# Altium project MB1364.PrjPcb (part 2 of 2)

## Sheet USB.SchDoc: USB
size A4; Date: Not used; ApprovedBy: Not used; CheckedBy: Not used; Author: Not used; CompanyName: STMicroelectronics; DrawnBy: Not used; Engineer: Not used; Organization: Not used; Address1: Not used; Address2: Not used; Address3: Not used; Address4: Not used; DocumentNumber: 7; Revision: Not used; SheetNumber: 7; SheetTotal: 9
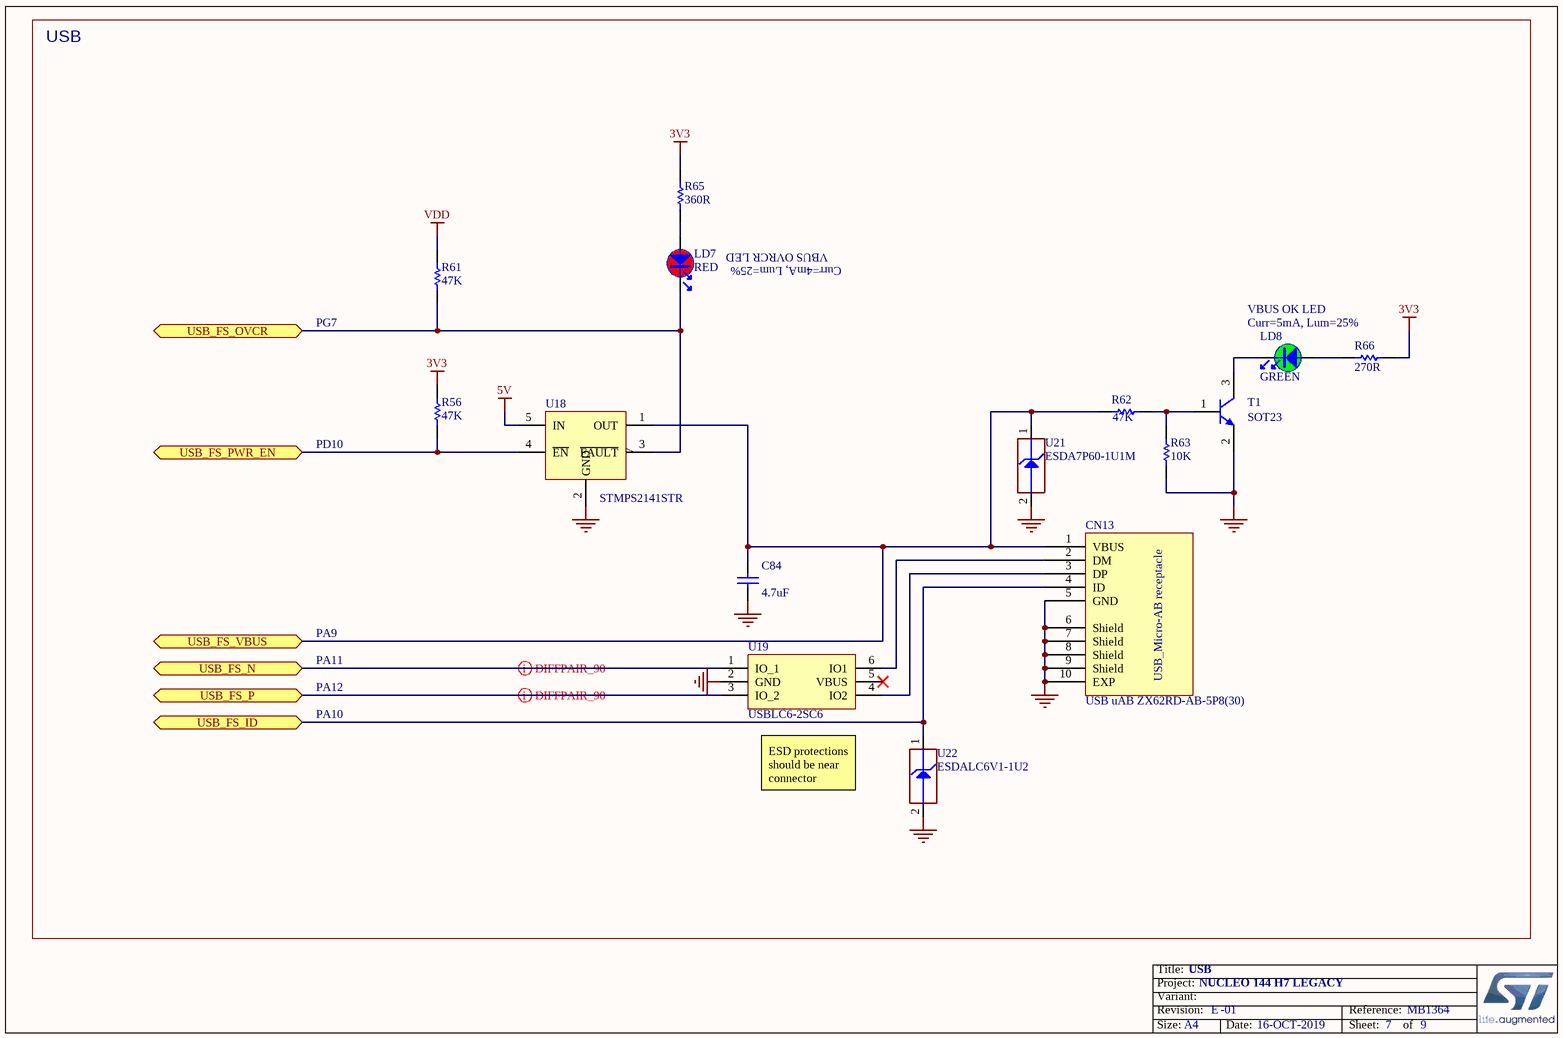
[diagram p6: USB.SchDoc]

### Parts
C84  value 4.7uF  [C0603]  (hidden comment: Capacitor)
CN13  value USB uAB ZX62RD-AB-5P8(30)  [CON_USBMICROAB_MOLEX_47590-0001_H3]  (hidden comment: USB_uAB_47590.0001)
LD7  value RED  [LED_0603_VISHAY_VLMS1300-GS08_RED_1A2K_H0P8]  (hidden comment: LED_red)
LD8  value GREEN  [LED_0603_OSRAM_LG-Q396-PS-35_GREEN_1A2K_H0P4]  (hidden comment: LED_green)
R56  value 47K  [R0402]  (hidden comment: Resistor)
R61  value 47K  [R0402]  (hidden comment: Resistor)
R62  value 47K  [R0402]  (hidden comment: Resistor)
R63  value 10K  [R0402]  (hidden comment: Resistor)
R65  value 360R  [R0402]  (hidden comment: Resistor)
R66  value 270R  [R0402]  (hidden comment: Resistor)
T1  value SOT23  [NPN_SOT23]  (hidden comment: 9013-SOT23)
U18  STMPS2141STR  [MOS_SOT23-5L]
U19  USBLC6-2SC6  [ESD_SOT23-6L]
U21  value ESDA7P60-1U1M  [ESD_QFN2_1P6X1_P125]  (hidden comment: ESD-TRANSIL)
U22  value ESDALC6V1-1U2  [ESD_ST0201]  (hidden comment: ESD-TRANSIL)

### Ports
USB_FS_ID, USB_FS_N, USB_FS_OVCR, USB_FS_P, USB_FS_PWR_EN, USB_FS_VBUS

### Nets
3V3: R56.1 R65.2 R66.2
5V: U18.5(IN)
GND: C84.1 CN13.5(GND) CN13.6(Shield) CN13.7(Shield) CN13.8(Shield) CN13.9(Shield) CN13.10(EXP) R63.1 T1.2(E) U18.2(GND) U19.2(GND) U21.2(GND) U22.2(GND)
VDD: R61.1
USB_FS_ID: CN13.4(ID) U22.1(IO1) ; port USB_FS_ID
USB_FS_N: U19.1(IO_1) ; port USB_FS_N
USB_FS_OVCR: LD7.2 R61.2 U18.3(~{FAULT}) ; port USB_FS_OVCR
USB_FS_P: U19.3(IO_2) ; port USB_FS_P
USB_FS_PWR_EN: R56.2 U18.4(~{EN}) ; port USB_FS_PWR_EN
USB_FS_VBUS: C84.2 CN13.1(VBUS) R62.1 U18.1(OUT) U21.1(IO1) ; port USB_FS_VBUS
NetCN13_2: CN13.2(DM) U19.6(IO1)
NetCN13_3: CN13.3(DP) U19.4(IO2)
NetLD7_1: LD7.1 R65.1
NetLD8_1: LD8.1 R66.1
NetLD8_2: LD8.2 T1.3(C)
NetR62_2: R62.2 R63.2 T1.1(B)

Not connected (* = marked no-connect by the designer): U19 5(VBUS)*

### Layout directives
differential pair: USB_FS_N, USB_FS_P

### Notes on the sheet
- USB
- VBUS OVRCR LED
- Curr=4mA, Lum=25%
- VBUS OK LED
- PG7
- Curr=5mA, Lum=25%
- PD10
- PA9
- PA11
- PA12
- PA10
- (near U19) ESD protections should be near connector

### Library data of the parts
C84 = MCD-00009: Capacitor, MLCC, 4.7uF, 16V, X5R, 10%, 0603, T=0.8mm; Manufacturer_Part_Number: CC0603KRX5R7BB475; Manufacturer: YAGEO; Provided_By: SUBCO; ECCN_US: EAR99; ECCN_EU: NEC
CN13 = MCD-00661: USB-MICRO-AB Receptacle, RA, SMT + DIP, Standard, Top Mount, USB certified (symbol & footprint compatible with MCD-00022); Part_Type: Connector; Manufacturer_Part_Number: ZX62RD-AB-5P8(30); Manufacturer: HIROSE; Provided_By: SUBCO
LD7 = MCD-00587: LED Red, 0603 SMD, 2V Forward Voltage; Part_Type: Display; Manufacturer_Part_Number: VLMS1300-GS08; Manufacturer: VISHAY; Alternate_Manufacturer_Part_Number: LS Q976-NR-1; Alternate_Manufacturer: OSRAM OPTO SEMICONDUCTORS; Provided_By: SUBCO
LD8 = MCD-00588: LED Green, 0603 SMD, Forward Voltage Typ=2V, Max=2.5V; Part_Type: Display; Manufacturer_Part_Number: LG Q396-PS-35; Manufacturer: OSRAM OPTO SEMICONDUCTORS; Alternate_Manufacturer_Part_Number: VLMTG1300-GS08; Alternate_Manufacturer: VISHAY SEMICONDUCTOR OPTO DIVISION; Provided_By: SUBCO
R56 R61 R62 = MCD-00063: Resistor,47K,0402,1%,1/16W; Manufacturer_Part_Number: RC0402FR-0747KL; Manufacturer: YAGEO; Provided_By: SUBCO; ECCN_US: EAR99; ECCN_EU: NEC
R63 = MCD-00053: Resistor,10K,0402,1%,1/16W; Manufacturer_Part_Number: RC0402FR-0710KL; Manufacturer: YAGEO; Provided_By: SUBCO; ECCN_US: EAR99; ECCN_EU: NEC
R65 = MCD-00461: Resistor,360R,0402,1%,1/16W; Manufacturer_Part_Number: RC0402FR-07360RL; Manufacturer: YAGEO; Provided_By: SUBCO; ECCN_US: EAR99; ECCN_EU: NEC
R66 = MCD-00441: Resistor,270R,0402,1%,1/16W; Manufacturer_Part_Number: RC0402FR-07270RL; Manufacturer: YAGEO; Provided_By: SUBCO; ECCN_US: EAR99; ECCN_EU: NEC
T1 = MCD-00073: NPN Bipolar Transistor; Manufacturer_Part_Number: BSR14; Manufacturer: ON SEMICONDUCTOR; Part_Type: IC; Alternate_Manufacturer_Part_Number: MMBT2222ALT1G / MMBT2222ALT3G; Provided_By: SUBCO; ECCN_US: EAR99; ECCN_EU: NEC
U18 = MCD-00083: Enhanced single channel power switches with active low enable pin; Part_Type: IC; Manufacturer: STMICROELECTRONICS; Alternate_Manufacturer_Part_Number: TPS2041C; Alternate_Manufacturer: TEXAS INSTRUMENTS; BMS_Part_Number: 9159003; Provided_By: SUBCO with ST control; ECCN_US: EAR99; ECCN_EU: NEC
U19 = MCD-00163: Very low capacitance ESD protection; Part_Type: IC; Manufacturer: STMICROELECTRONICS; BMS_Part_Number: 9151075; Provided_By: SUBCO with ST control; ECCN_US: EAR99; ECCN_EU: NEC
U21 = MCD-00251: High power transient voltage suppressor, 7V breakdown; Part_Type: Diode; Manufacturer: STMICROELECTRONICS; BMS_Part_Number: 9179042; Provided_By: SUBCO with ST control; ECCN_US: EAR99; ECCN_EU: NEC
U22 = MCD-00170: ESD protection 6V1; Part_Type: Diode; Manufacturer: STMICROELECTRONICS; BMS_Part_Number: 9151132; Provided_By: SUBCO with ST control; ECCN_US: EAR99; ECCN_EU: NEC

## Sheet Ethernet.SchDoc: Ethernet PHY with RJ45 connector
size A4; Date: Not used; ApprovedBy: Not used; CheckedBy: Not used; Author: Not used; CompanyName: STMicroelectronics; DrawnBy: Not used; Engineer: Not used; Organization: Not used; Address1: Not used; Address2: Not used; Address3: Not used; Address4: Not used; DocumentNumber: 6; Revision: Not used; SheetNumber: 6; SheetTotal: 9
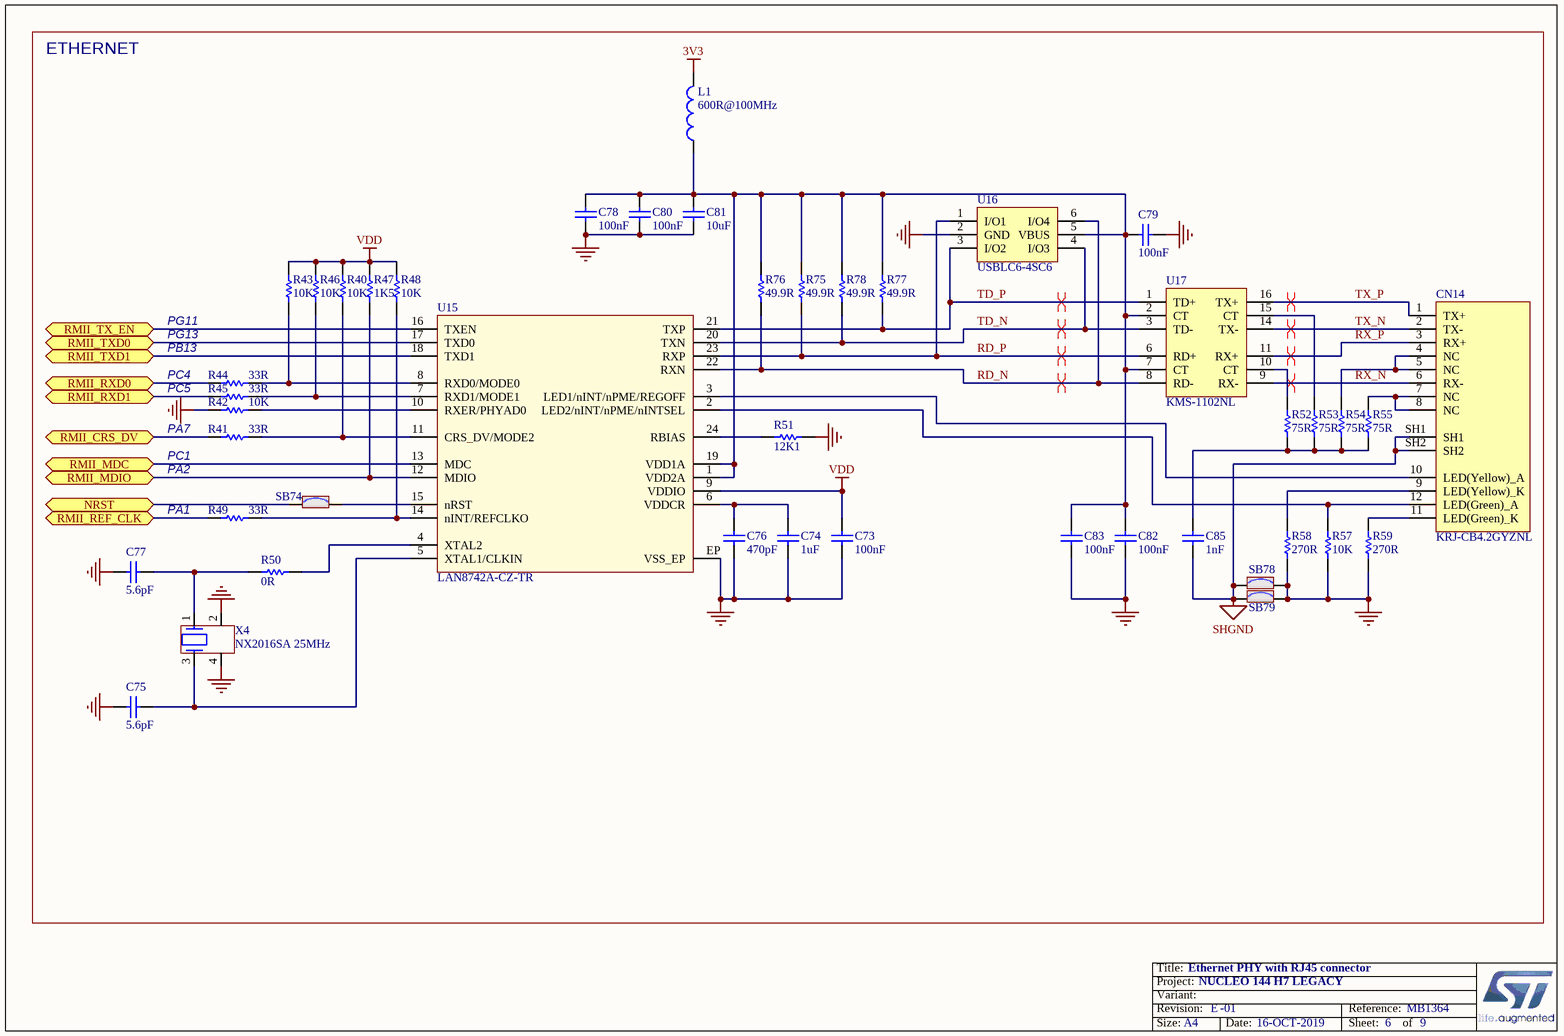
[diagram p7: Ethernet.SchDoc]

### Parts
C73  value 100nF  [C0603]  (hidden comment: Capacitor)
C74  value 1uF  [C0402]  (hidden comment: Capacitor)
C75  value 5.6pF  [C0402]  (hidden comment: Capacitor)
C76  value 470pF  [C0402]  (hidden comment: Capacitor)
C77  value 5.6pF  [C0402]  (hidden comment: Capacitor)
C78  value 100nF  [C0603]  (hidden comment: Capacitor)
C79  value 100nF  [C0603]  (hidden comment: Capacitor)
C80  value 100nF  [C0603]  (hidden comment: Capacitor)
C81  value 10uF  [C0603]  (hidden comment: Capacitor)
C82  value 100nF  [C0603]  (hidden comment: Capacitor)
C83  value 100nF  [C0603]  (hidden comment: Capacitor)
C85  value 1nF  [C1206_H1P6]  (hidden comment: Capacitor)
CN14  value KRJ-CB4.2GYZNL  [CON_RJ45_DGKYD_KRJ-CB4.2GYZNL]  (hidden comment: RJ45_KRJ-CB4.2GYZNL)
L1  value 600R@100MHz  [L0603]  (hidden comment: BEAD)
R40  value 10K  [R0402]  (hidden comment: Resistor)
R41  value 33R  [R0402]  (hidden comment: Resistor)
R42  value 10K  [R0402]  (hidden comment: Resistor)
R43  value 10K  [R0402]  (hidden comment: Resistor)
R44  value 33R  [R0402]  (hidden comment: Resistor)
R45  value 33R  [R0402]  (hidden comment: Resistor)
R46  value 10K  [R0402]  (hidden comment: Resistor)
R47  value 1K5  [R0402]  (hidden comment: Resistor)
R48  value 10K  [R0402]  (hidden comment: Resistor)
R49  value 33R  [R0402]  (hidden comment: Resistor)
R50  value 0R  [R0402]  (hidden comment: Resistor)
R51  value 12K1  [R0402]  (hidden comment: Resistor)
R52  value 75R  [R0402]  (hidden comment: Resistor)
R53  value 75R  [R0402]  (hidden comment: Resistor)
R54  value 75R  [R0402]  (hidden comment: Resistor)
R55  value 75R  [R0402]  (hidden comment: Resistor)
R57  value 10K  [R0402]  (hidden comment: Resistor)
R58  value 270R  [R0402]  (hidden comment: Resistor)
R59  value 270R  [R0402]  (hidden comment: Resistor)
R75  value 49.9R  [R0402]  (hidden comment: Resistor)
R76  value 49.9R  [R0402]  (hidden comment: Resistor)
R77  value 49.9R  [R0402]  (hidden comment: Resistor)
R78  value 49.9R  [R0402]  (hidden comment: Resistor)
SB74  SB_ON  [SOLDER-BRIDGE_R0603-0R]  (value not drawn)
SB78  SB_ON  [SOLDER-BRIDGE_R0603-0R]  (value not drawn)
SB79  SB_ON  [SOLDER-BRIDGE_R0603-0R]  (value not drawn)
U15  LAN8742A-CZ-TR  [ICC_VQFN24-EPAD_4X4_P050]
U16  USBLC6-4SC6  [ESD_SOT23-6L]
U17  KMS-1102NL  [TRS_DGKYD_KMS-1102NL]
X4  value NX2016SA 25MHz  [CRY_NX2016SA_4P]  (hidden comment: XTAL_4_PINS)

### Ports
NRST (bidir), RMII_CRS_DV (bidir), RMII_MDC (bidir), RMII_MDIO (bidir), RMII_REF_CLK (bidir), RMII_RXD0 (bidir), RMII_RXD1 (bidir), RMII_TX_EN (bidir), RMII_TXD0 (bidir), RMII_TXD1 (bidir)

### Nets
3V3: L1.2
GND: C73.1 C74.1 C75.1 C76.1 C77.1 C78.1 C79.2 C80.1 C81.1 C82.1 C83.1 R42.2 R51.2 R57.1 R58.1 R59.1 SB78.2 SB79.2 U15.EP(VSS_EP) U16.2(GND) X4.2 X4.4
SHGND: C85.1 CN14.SH1 CN14.SH2 SB78.1 SB79.1
VDD: C73.2 R40.2 R43.2 R46.2 R47.2 R48.2 U15.9(VDDIO)
NRST: SB74.1 ; port NRST
RD_N: R76.1 U15.22(RXN) U16.6(I/O4) U17.8(RD-)
RD_P: R75.1 U15.23(RXP) U16.1(I/O1) U17.6(RD+)
RMII_CRS_DV: R41.1 ; port RMII_CRS_DV
RMII_MDC: U15.13(MDC) ; port RMII_MDC
RMII_MDIO: R47.1 U15.12(MDIO) ; port RMII_MDIO
RMII_REF_CLK: R49.1 ; port RMII_REF_CLK
RMII_RXD0: R44.1 ; port RMII_RXD0
RMII_RXD1: R45.1 ; port RMII_RXD1
RMII_TX_EN: U15.16(TXEN) ; port RMII_TX_EN
RMII_TXD0: U15.17(TXD0) ; port RMII_TXD0
RMII_TXD1: U15.18(TXD1) ; port RMII_TXD1
RX_N: CN14.6(RX-) U17.9(RX-)
RX_P: CN14.3(RX+) U17.11(RX+)
TD_N: R78.1 U15.20(TXN) U16.4(I/O3) U17.3(TD-)
TD_P: R77.1 U15.21(TXP) U16.3(I/O2) U17.1(TD+)
TX_N: CN14.2(TX-) U17.14(TX-)
TX_P: CN14.1(TX+) U17.16(TX+)
NetC74_2: C74.2 C76.2 U15.6(VDDCR)
NetC75_2: C75.2 U15.5(XTAL1/CLKIN) X4.3
NetC77_2: C77.2 R50.1 X4.1
NetC78_2: C78.2 C79.1 C80.2 C81.2 C82.2 C83.2 L1.1 R75.2 R76.2 R77.2 R78.2 U15.1(VDD2A) U15.19(VDD1A) U16.5(VBUS) U17.2(CT) U17.7(CT)
NetC85_2: C85.2 R52.1 R53.1 R54.1 R55.1
NetCN14_4: CN14.4(NC) CN14.5(NC) R54.2
NetCN14_7: CN14.7(NC) CN14.8(NC) R55.2
NetCN14_9: CN14.9(LED(Yellow)_K) R58.2
NetCN14_10: CN14.10(LED(Yellow)_A) U15.3(LED1/nINT/nPME/REGOFF)
NetCN14_11: CN14.11(LED(Green)_K) R59.2
NetCN14_12: CN14.12(LED(Green)_A) R57.2 U15.2(LED2/nINT/nPME/nINTSEL)
NetR40_1: R40.1 R41.2 U15.11(CRS_DV/MODE2)
NetR42_1: R42.1 U15.10(RXER/PHYAD0)
NetR43_1: R43.1 R44.2 U15.8(RXD0/MODE0)
NetR45_2: R45.2 R46.1 U15.7(RXD1/MODE1)
NetR48_1: R48.1 R49.2 U15.14(nINT/REFCLKO)
NetR50_2: R50.2 U15.4(XTAL2)
NetR51_1: R51.1 U15.24(RBIAS)
NetR52_2: R52.2 U17.10(CT)
NetR53_2: R53.2 U17.15(CT)
NetSB74_2: SB74.2 U15.15(nRST)

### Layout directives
differential pair: RD_N, RD_P, RX_N, RX_P, TD_N, TD_P, TX_N, TX_P

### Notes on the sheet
- ETHERNET
- PG11
- PG13
- PB13
- PC4
- PC5
- PA7
- PC1
- PA2
- (near R49) PA1

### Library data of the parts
C73 C78-C80 C82 C83 = MCD-00237: Capacitor, MLCC, 100nF, 6V3, X5R, 10%, 0603, T=0,8mm; Manufacturer_Part_Number: CC0603KRX5R5BB104; Manufacturer: YAGEO; Provided_By: SUBCO; ECCN_US: EAR99; ECCN_EU: NEC
C74 = MCD-00095: Capacitor, MLCC, 1uF, 6V3, X5R, 10%, 0402, T=0,5mm; Manufacturer_Part_Number: GRM155R61E105KA12; Manufacturer: MURATA; Alternate_Manufacturer_Part_Number: GRM155R60J105KE19; Provided_By: SUBCO; ECCN_US: EAR99; ECCN_EU: NEC
C75 C77 = MCD-01374: Capacitor, MLCC, 5.6pF, 50V, NPO, 5%, 0402, T=0,5mm; Manufacturer_Part_Number: CC0402BRNPO9BN5R6; Manufacturer: YAGEO; Provided_By: SUBCO
C76 = MCD-00724: Capacitor, MLCC, 470pF, 50V, NPO, 5%, 0402, T=0,5mm; Manufacturer_Part_Number: CC0402JRNPO9BN471; Manufacturer: YAGEO; Provided_By: SUBCO
C81 = MCD-01124: Capacitor, MLCC, 10µF, 10V, X5R, 10%, 0603, T=0.8mm; Manufacturer_Part_Number: GRM188R61A106KAAL; Manufacturer: MURATA; Provided_By: SUBCO; ECCN_US: EAR99; ECCN_EU: NEC
C85 = MCD-00722: Capacitor, MLCC, 1nF, 2KV, X7R, 10%, 1206, T=1,25mm; Manufacturer_Part_Number: CC1206KKX7RDBB102; Manufacturer: YAGEO; Provided_By: SUBCO
CN14 = MCD-00717: RJ45 jack, single port, with LEDS, Metal shielded dip low profile; Part_Type: Connector; Manufacturer: DONGGUAN KEYOUDA ELECTRONIC TECHNOLOGY; Provided_By: SUBCO
L1 = MCD-00047: SMD Chip ferrite bead, 600R@100MHz +/-25%, 350mA, 500mohm DC, 0603, T=0.8mm; Part_Type: Inductor; Manufacturer_Part_Number: FCM1608KF-601T03; Manufacturer: TAI-TECH; Provided_By: SUBCO
R40 R42 R43 R46 R48 R57 = MCD-00053: as R63 on sheet USB
R41 R44 R45 R49 = MCD-00455: Resistor,33R,0402,1%,1/16W; Manufacturer_Part_Number: RC0402FR-0733RL; Manufacturer: YAGEO; Provided_By: SUBCO; ECCN_US: EAR99; ECCN_EU: NEC
R47 = MCD-00068: Resistor,1K5,0402,1%,1/16W; Manufacturer_Part_Number: RC0402FR-071K5L; Manufacturer: YAGEO; Provided_By: SUBCO; ECCN_US: EAR99; ECCN_EU: NEC
R50 = MCD-00052: Resistor,0R,0402,5%,1/16W; Manufacturer_Part_Number: RC0402JR-070RL; Manufacturer: YAGEO; Provided_By: SUBCO; ECCN_US: EAR99; ECCN_EU: NEC
R51 = MCD-00723: Resistor,12K1,0402,1%,1/16W; Manufacturer_Part_Number: RC0402FR-0712K1L; Manufacturer: YAGEO; Provided_By: SUBCO; ECCN_US: EAR99; ECCN_EU: NEC
R52-R55 = MCD-00515: Resistor,75R,0402,1%,1/16W; Manufacturer_Part_Number: RC0402FR-0775RL; Manufacturer: YAGEO; Provided_By: SUBCO; ECCN_US: EAR99; ECCN_EU: NEC
R58 R59 = MCD-00441: as R66 on sheet USB
R75-R78 = MCD-00565: Resistor,49R9,0402,1%,1/16W; Manufacturer_Part_Number: RC0402FR-0749R9L; Manufacturer: YAGEO; Provided_By: SUBCO; ECCN_US: EAR99; ECCN_EU: NEC
SB74 SB78 SB79 = MCD-00071: Solder Bridge ON; Part_Type: Mechanical; Manufacturer_Part_Number: RC0603JR-070RL; Manufacturer: YAGEO; Provided_By: SUBCO
U15 = MCD-00719: 10/100M RMII Ethernet transceiver; Part_Type: IC; Manufacturer: MICROCHIP; Provided_By: SUBCO
U16 = MCD-00250: Very low capacitance ESD protection , 4 lines; Part_Type: IC; Manufacturer: STMICROELECTRONICS; BMS_Part_Number: 9151001; Provided_By: SUBCO with ST control; ECCN_US: EAR99; ECCN_EU: NEC
U17 = MCD-00718: Discrete Magnetic Transformer Module, 16 pins, SMT, 100 Base-TX; Part_Type: IC; Manufacturer: DONGGUAN KEYOUDA ELECTRONIC TECHNOLOGY; Provided_By: SUBCO
X4 = MCD-01364: Crystal 25MHz, 6pF, +-20ppm, 80ohms max, SMD; Part_Type: Crystal_Osc; Manufacturer_Part_Number: NX2016SA 25MHz EXS00A-CS11321; Manufacturer: NDK; BMS_Part_Number: 9157044; Provided_By: SUBCO; ECCN_US: EAR99; ECCN_EU: NEC

## Sheet ST_LINK_V3E.SchDoc: STLINK_V3E
size A3; Date: Not used; ApprovedBy: Not used; CheckedBy: Not used; Author: Not used; CompanyName: STMicroelectronics; DrawnBy: Not used; Engineer: Not used; Organization: Not used; Address1: Not used; Address2: Not used; Address3: Not used; Address4: Not used; DocumentNumber: 10; Revision: Not used; SheetNumber: 9; SheetTotal: 9
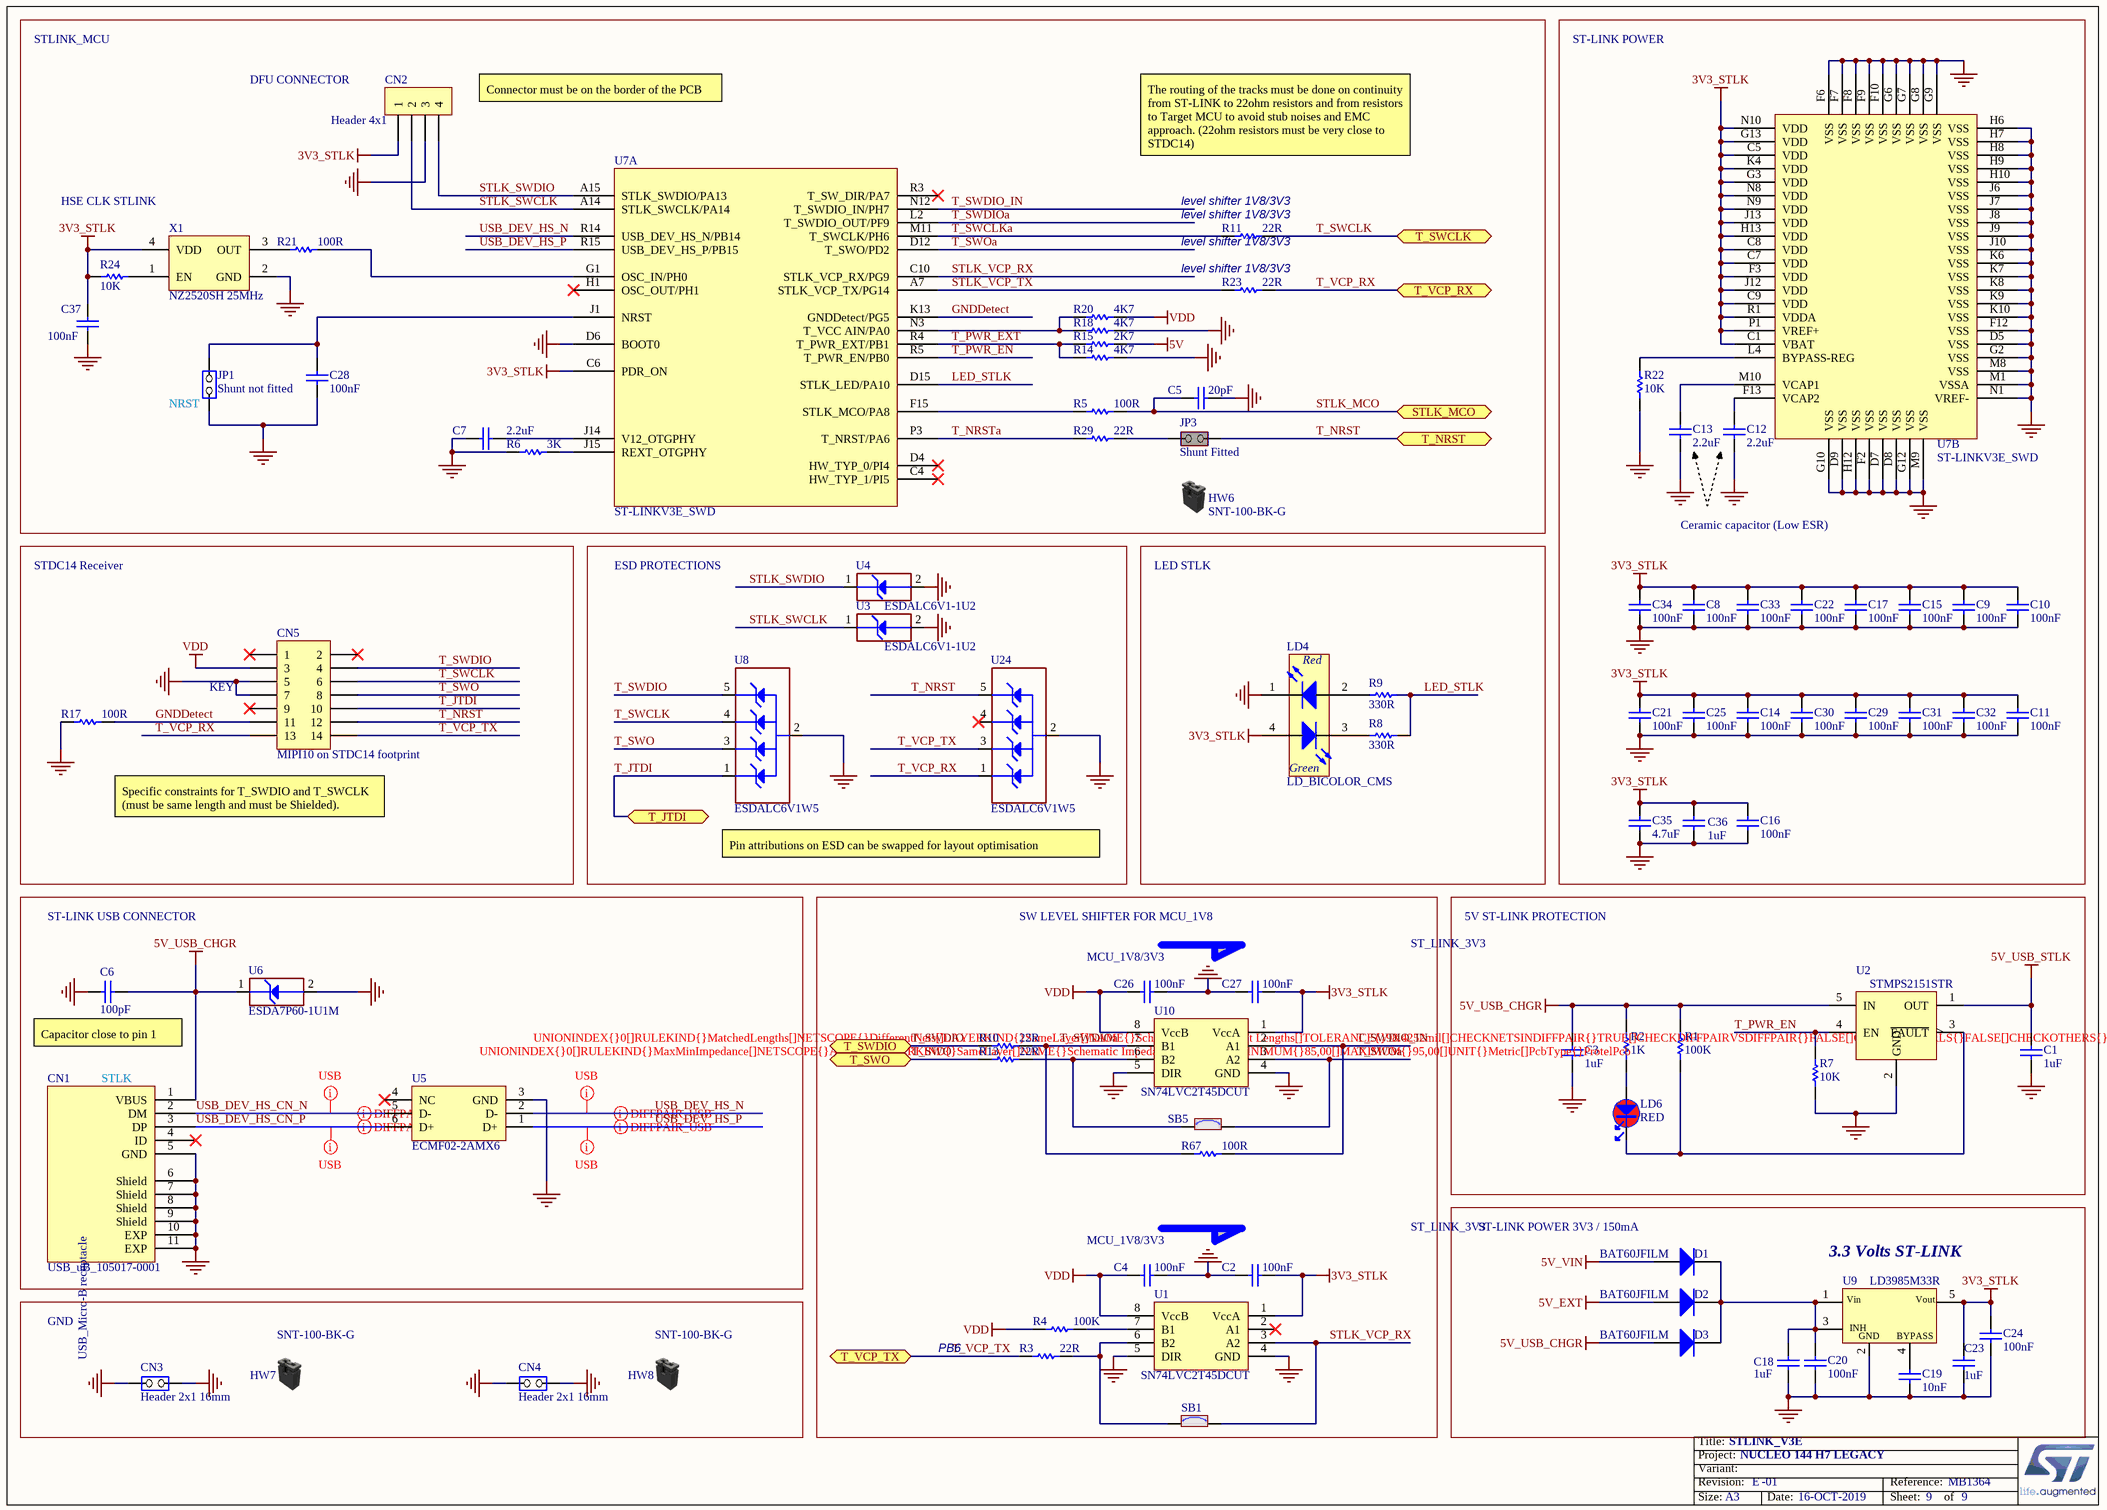
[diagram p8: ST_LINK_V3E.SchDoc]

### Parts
C1  value 1uF  [C0603]  (hidden comment: Capacitor)
C2  value 100nF  [C0603]  (hidden comment: Capacitor)
C3  value 1uF  [C0603]  (hidden comment: Capacitor)
C4  value 100nF  [C0603]  (hidden comment: Capacitor)
C5  value 20pF  [C0402]  (hidden comment: Capacitor)
C6  value 100pF  [C0402]  (hidden comment: Capacitor)
C7  value 2.2uF  [C0603]  (hidden comment: Capacitor)
C8  value 100nF  [C0402]  (hidden comment: Capacitor)
C9  value 100nF  [C0402]  (hidden comment: Capacitor)
C10  value 100nF  [C0402]  (hidden comment: Capacitor)
C11  value 100nF  [C0402]  (hidden comment: Capacitor)
C12  value 2.2uF  [C0603]  (hidden comment: Capacitor)
C13  value 2.2uF  [C0603]  (hidden comment: Capacitor)
C14  value 100nF  [C0402]  (hidden comment: Capacitor)
C15  value 100nF  [C0402]  (hidden comment: Capacitor)
C16  value 100nF  [C0402]  (hidden comment: Capacitor)
C17  value 100nF  [C0402]  (hidden comment: Capacitor)
C18  value 1uF  [C0603]  (hidden comment: Capacitor)
C19  value 10nF  [C0402]  (hidden comment: Capacitor)
C20  value 100nF  [C0402]  (hidden comment: Capacitor)
C21  value 100nF  [C0402]  (hidden comment: Capacitor)
C22  value 100nF  [C0402]  (hidden comment: Capacitor)
C23  value 1uF  [C0603]  (hidden comment: Capacitor)
C24  value 100nF  [C0402]  (hidden comment: Capacitor)
C25  value 100nF  [C0402]  (hidden comment: Capacitor)
C26  value 100nF  [C0603]  (hidden comment: Capacitor)
C27  value 100nF  [C0603]  (hidden comment: Capacitor)
C28  value 100nF  [C0402]  (hidden comment: Capacitor)
C29  value 100nF  [C0402]  (hidden comment: Capacitor)
C30  value 100nF  [C0402]  (hidden comment: Capacitor)
C31  value 100nF  [C0402]  (hidden comment: Capacitor)
C32  value 100nF  [C0402]  (hidden comment: Capacitor)
C33  value 100nF  [C0402]  (hidden comment: Capacitor)
C34  value 100nF  [C0402]  (hidden comment: Capacitor)
C35  value 4.7uF  [C0603]  (hidden comment: Capacitor)
C36  value 1uF  [C0603]  (hidden comment: Capacitor)
C37  value 100nF  [C0402]  (hidden comment: Capacitor)
CN1  value USB_uB_105017-0001  [CON_USBMICROB_MOLEX_105017-0001_H2P90]  (hidden comment: USB_uB_105017.0001)
CN2  Header 4x1  [CON_SAMTEC_TSW-104-07-G-S]
CN3  value Header 2x1 16mm  [CON_SAMTEC_TSW-102-09-X-S]  (hidden comment: Jumper_Header 2x1)
CN4  value Header 2x1 16mm  [CON_SAMTEC_TSW-102-09-X-S]  (hidden comment: Jumper_Header 2x1)
CN5  value MIPI10 on STDC14 footprint  [CON_STDC14_Receiver_MEDIUM_WITH_MIPI10_3D]  (hidden comment: Header 7x2)
D1  BAT60JFILM  [DIO_SOD323]
D2  BAT60JFILM  [DIO_SOD323]
D3  BAT60JFILM  [DIO_SOD323]
HW6  value SNT-100-BK-G  (hidden comment: Shunt Black 2.54mm)  (mechanical)
HW7  value SNT-100-BK-G  (hidden comment: Shunt Black 2.54mm)  (mechanical)
HW8  value SNT-100-BK-G  (hidden comment: Shunt Black 2.54mm)  (mechanical)
JP1  value Shunt not fitted  [CON_SAMTEC_TSW-102-07-G-S]  (hidden comment: Jumper_Header 2x1)
JP3  value Shunt Fitted  [CON_SAMTEC_TSW-102-07-G-S]  (hidden comment: Jumper_Header 2x1 Fitted)
LD4  LD_BICOLOR_CMS  [LED_BI-GR_HSMF-A201-A00J1]
LD6  value RED  [LED_0603_RED]  (hidden comment: LED_red)
R1  value 100K  [R0603]  (hidden comment: Resistor)
R2  value 1K  [R0603]  (hidden comment: Resistor)
R3  value 22R  [R0402]  (hidden comment: Resistor)
R4  value 100K  [R0603]  (hidden comment: Resistor)
R5  value 100R  [R0402]  (hidden comment: Resistor)
R6  value 3K  [R0402]  (hidden comment: Resistor)
R7  value 10K  [R0603]  (hidden comment: Resistor)
R8  value 330R  [R0603]  (hidden comment: Resistor)
R9  value 330R  [R0603]  (hidden comment: Resistor)
R10  value 22R  [R0402]  (hidden comment: Resistor)
R11  value 22R  [R0402]  (hidden comment: Resistor)
R13  value 22R  [R0402]  (hidden comment: Resistor)
R14  value 4K7  [R0402]  (hidden comment: Resistor)
R15  value 2K7  [R0402]  (hidden comment: Resistor)
R17  value 100R  [R0402]  (hidden comment: Resistor)
R18  value 4K7  [R0402]  (hidden comment: Resistor)
R20  value 4K7  [R0402]  (hidden comment: Resistor)
R21  value 100R  [R0402]  (hidden comment: Resistor)
R22  value 10K  [R0402]  (hidden comment: Resistor)
R23  value 22R  [R0402]  (hidden comment: Resistor)
R24  value 10K  [R0402]  (hidden comment: Resistor)
R29  value 22R  [R0402]  (hidden comment: Resistor)
R67  value 100R  [R0402]  (hidden comment: Resistor)
SB1  SB_ON  [SOLDER-BRIDGE_R0603-0R]  (value not drawn)
SB5  SB_ON  [SOLDER-BRIDGE_R0603-0R]  (value not drawn)
U1  SN74LVC2T45DCUT  [ICC_VSSOP8_DCU_R-PDSO-G8_2X2P30_P050]
U2  STMPS2151STR  [MOS_SOT23-5L]
U3  value ESDALC6V1-1U2  [ESD_ST0201]  (hidden comment: ESD-TRANSIL)
U4  value ESDALC6V1-1U2  [ESD_ST0201]  (hidden comment: ESD-TRANSIL)
U5  ECMF02-2AMX6  [ESD_QFN-6L_1P7X1P5_P050]
U6  value ESDA7P60-1U1M  [ESD_QFN2_1P6X1_P125]  (hidden comment: ESD-TRANSIL)
U7  ST-LINKV3E_SWD  [ICC_UFBGA201_176+25_10X10_P065]  (parts A,B of 2)
U8  ESDALC6V1W5  [ESD_SOT323-5L]
U9  LD3985M33R  [REG_SOT23-5L]
U10  SN74LVC2T45DCUT  [ICC_VSSOP8_DCU_R-PDSO-G8_2X2P30_P050]
U24  ESDALC6V1W5  [ESD_SOT323-5L]
X1  value NZ2520SH 25MHz  [OSC_NDK_NZ2520SB_4P]  (hidden comment: OSCILLATOR_4_PINS)

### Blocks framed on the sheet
ESD PROTECTIONS: U3 U4 U8 U24
LED STLK: LD4 R8 R9
5V ST-LINK PROTECTION: C1 C3 LD6 R1 R2 R7 U2
3.3 Volts ST-LINK: C18-C20 C23 C24 D1-D3 U9
GND: CN3 CN4 HW7 HW8

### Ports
STLK_MCO, T_JTDI (bidir), T_NRST, T_SWCLK, T_SWDIO, T_SWO, T_VCP_RX, T_VCP_TX

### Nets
3V3_STLK: C2.2 C8.2 C9.2 C10.2 C11.2 C14.2 C15.2 C16.2 C17.2 C21.2 C22.2 C23.2 C24.2 C25.2 C27.2 C29.2 C30.2 C31.2 C32.2 C33.2 C34.2 C35.2 C36.2 C37.2 CN2.1 LD4.4(YellowGreen_anode) R24.1 U1.1(VccA) U7.C1(VBAT) U7.C5(VDD) U7.C6(PDR_ON) U7.C7(VDD) U7.C8(VDD) U7.C9(VDD) U7.F3(VDD) U7.G3(VDD) U7.G13(VDD) U7.H13(VDD) U7.J12(VDD) U7.J13(VDD) U7.K4(VDD) U7.N8(VDD) U7.N9(VDD) U7.N10(VDD) U7.P1(VREF+) U7.R1(VDDA) U9.5(Vout) U10.1(VccA) X1.4(VDD)
5V: R15.1
5V_EXT: D2.1(A)
5V_USB_CHGR: C3.2 C6.2 CN1.1(VBUS) D3.1(A) R1.2 R2.2 U2.5(IN) U6.1(IO1)
5V_USB_STLK: C1.2 U2.1(OUT)
5V_VIN: D1.1(A)
GND: C1.1 C2.1 C3.1 C4.2 C5.1 C6.1 C7.1 C8.1 C9.1 C10.1 C11.1 C12.1 C13.1 C14.1 C15.1 C16.1 C17.1 C18.2 C19.1 C20.1 C21.1 C22.1 C23.1 C24.1 C25.1 C26.2 C27.1 C28.1 C29.1 C30.1 C31.1 C32.1 C33.1 C34.1 C35.1 C36.1 C37.1 CN1.5(GND) CN1.6(Shield) CN1.7(Shield) CN1.8(Shield) CN1.9(Shield) CN1.10(EXP) CN1.11(EXP) CN2.3 CN3.1(COMMON) CN3.2(NO) CN4.1(COMMON) CN4.2(NO) CN5.5 CN5.7 JP1.1(COMMON) LD4.1(RED_cathode) R6.1 R7.2 R14.1 R17.1 R18.2 R22.1 U1.4(GND) U1.5(DIR) U2.2(GND) U3.2(GND) U4.2(GND) U5.3(GND) U6.2(GND) U7.D5(VSS) U7.D6(BOOT0) U7.D7(VSS) U7.D8(VSS) U7.D9(VSS) U7.F2(VSS) U7.F6(VSS) U7.F7(VSS) U7.F8(VSS) U7.F9(VSS) U7.F10(VSS) U7.F12(VSS) U7.G2(VSS) U7.G6(VSS) U7.G7(VSS) U7.G8(VSS) U7.G9(VSS) U7.G10(VSS) U7.G12(VSS) U7.H6(VSS) U7.H7(VSS) U7.H8(VSS) U7.H9(VSS) U7.H10(VSS) U7.H12(VSS) U7.J6(VSS) U7.J7(VSS) U7.J8(VSS) U7.J9(VSS) U7.J10(VSS) U7.K6(VSS) U7.K7(VSS) U7.K8(VSS) U7.K9(VSS) U7.K10(VSS) U7.M1(VSSA) U7.M8(VSS) U7.M9(VSS) U7.N1(VREF-) U8.2(GND) U9.2(GND) U10.4(GND) U10.5(DIR) U24.2(GND) X1.2(GND)
VDD: C4.1 C26.1 CN5.3 R4.1 R20.2 U1.8(VccB) U10.8(VccB)
GNDDetect: CN5.11 R17.2 U7.K13(GNDDetect/PG5)
LED_STLK: R8.2 R9.2 U7.D15(STLK_LED/PA10)
STLK_MCO: C5.2 R5.2 ; port STLK_MCO
STLK_SWCLK: CN2.2 U3.1(IO1) U7.A14(STLK_SWCLK/PA14)
STLK_SWDIO: CN2.4 U4.1(IO1) U7.A15(STLK_SWDIO/PA13)
STLK_VCP_RX: SB1.2 U1.3(A2) U7.C10(STLK_VCP_RX/PG9)
STLK_VCP_TX: R23.1 U7.A7(STLK_VCP_TX/PG14)
T_JTDI: CN5.10 U8.1(IO1) ; port T_JTDI  [project net PA15]
T_NRST: CN5.12 JP3.2(NO) U24.5(IO4) ; port T_NRST
T_NRSTa: R29.1 U7.P3(T_NRST/PA6)
T_PWR_EN: R7.1 U2.4(EN) U7.R5(T_PWR_EN/PB0)
T_PWR_EXT: R14.2 R15.2 U7.R4(T_PWR_EXT/PB1)
T_SWCLK: CN5.6 R11.2 U8.4(IO3) ; port T_SWCLK
T_SWCLKa: R11.1 U7.M11(T_SWCLK/PH6)
T_SWDIO: CN5.4 R10.1 U8.5(IO4) ; port T_SWDIO
T_SWDIO_IN: R67.2 U7.N12(T_SWDIO_IN/PH7) U10.2(A1)
T_SWDIOa: R10.2 R67.1 U7.L2(T_SWDIO_OUT/PF9) U10.7(B1)
T_SWO: CN5.8 R13.1 U8.3(IO2) ; port T_SWO
T_SWOa: SB5.1 U7.D12(T_SWO/PD2) U10.3(A2)
T_VCP_RX: CN5.13 R23.2 U24.1(IO1) ; port T_VCP_RX
T_VCP_TX: CN5.14 R3.1 U24.3(IO2) ; port T_VCP_TX
USB_DEV_HS_CN_N: CN1.2(DM) U5.5(D-)
USB_DEV_HS_CN_P: CN1.3(DP) U5.6(D+)
USB_DEV_HS_N: U5.2(D-) U7.R14(USB_DEV_HS_N/PB14)
USB_DEV_HS_P: U5.1(D+) U7.R15(USB_DEV_HS_P/PB15)
NetC7_2: C7.2 U7.J14(V12_OTGPHY)
NetC12_2: C12.2 U7.F13(VCAP2)
NetC13_2: C13.2 U7.M10(VCAP1)
NetC18_1: C18.1 C20.2 D1.2(K) D2.2(K) D3.2(K) U9.1(Vin) U9.3(CE)
NetC19_2: C19.2 U9.4(BYPASS)
NetC28_2: C28.2 JP1.2(NO) U7.J1(NRST)
NetJP3_1: JP3.1(COMMON) R29.2
NetLD4_2: LD4.2(Red_anode) R9.1
NetLD4_3: LD4.3(YellowGreen_cathode) R8.1
NetLD6_1: LD6.1 R2.1
NetLD6_2: LD6.2 R1.1 U2.3(~{FAULT})
NetR3_2: R3.2 SB1.1 U1.6(B2)
NetR4_2: R4.2 U1.7(B1)
NetR5_1: R5.1 U7.F15(STLK_MCO/PA8)
NetR6_2: R6.2 U7.J15(REXT_OTGPHY)
NetR13_2: R13.2 SB5.2 U10.6(B2)
NetR18_1: R18.1 R20.1 U7.N3(T_VCC_AIN/PA0)
NetR21_1: R21.1 X1.3(OUT)
NetR21_2: R21.2 U7.G1(OSC_IN/PH0)
NetR22_2: R22.2 U7.L4(BYPASS-REG)
NetR24_2: R24.2 X1.1(EN)

Not connected (* = marked no-connect by the designer): CN1 4(ID)*; CN5 1* 2* 9*; U1 2(A1)*; U5 4(NC)*; U7 C4(HW_TYP_1/PI5)* D4(HW_TYP_0/PI4)* H1(OSC_OUT/PH1)* R3(T_SW_DIR/PA7)*; U24 4(IO3)*

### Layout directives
differential pair; rule Impedance Constraint [Min = 85.00    Max = 95.00    ]: USB_DEV_HS_CN_N, USB_DEV_HS_CN_P, USB_DEV_HS_N, USB_DEV_HS_P
rule Undefined; rule Matched Net Lengths [Tolerance = 2.5mm]; rule Impedance Constraint [Min = 85.00    Max = 95.00    ]: USB_DEV_HS_N
rule Undefined; rule Matched Net Lengths [Tolerance = 0.2mm]; rule Impedance Constraint [Min = 85.00    Max = 95.00    ]: USB_DEV_HS_CN_N, USB_DEV_HS_CN_P, USB_DEV_HS_P

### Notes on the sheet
- STLINK_MCU
- ST-LINK POWER
- DFU CONNECTOR
- (near CN2) Connector must be on the border of the PCB
- The routing of the tracks must be done on continuity from ST-LINK to 22ohm resistors and from resistors to Target MCU to avoid stub noises and EMC approach. (22ohm resistors must be very close to STDC14)
- HSE CLK STLINK
- level shifter 1V8/3V3
- (near JP1) NRST
- STDC14 Receiver
- Ceramic capacitor (Low ESR)
- (near CN5) KEY
- Specific constraints for T_SWDIO and T_SWCLK (must be same length and must be Shielded).
- Pin attributions on ESD can be swapped for layout optimisation
- ST-LINK USB CONNECTOR
- SW LEVEL SHIFTER FOR MCU_1V8
- MCU_1V8/3V3
- ST_LINK_3V3
- (near C6) Capacitor close to pin 1
- (near CN1) STLK
- ST-LINK POWER 3V3 / 150mA
- PB6

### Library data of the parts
C1 C3 C18 = MCD-00238: Capacitor, MLCC, 1uF, 6V3, X5R, 10%, 0603, T=0,8mm; Manufacturer_Part_Number: CC0603KRX5R5BB105; Manufacturer: YAGEO; Provided_By: SUBCO; ECCN_US: EAR99; ECCN_EU: NEC
C2 C4 C26 C27 = MCD-00237: as C73 on sheet Ethernet
C5 = MCD-00016: Capacitor, MLCC, 20pF, 50V, NPO, 5%, 0402, T=0,5mm; Manufacturer_Part_Number: CC0402JRNPO9BN200; Manufacturer: YAGEO; Provided_By: SUBCO; ECCN_US: EAR99; ECCN_EU: NEC
C6 = MCD-00205: Capacitor, MLCC, 100pF, 50V, NPO, 5%, 0402, T=0,5mm; Manufacturer_Part_Number: CC0402JRNPO9BN101; Manufacturer: YAGEO; Provided_By: SUBCO; ECCN_US: EAR99; ECCN_EU: NEC
C7 C12 C13 = MCD-00012: Capacitor, MLCC, 2.2uF, 10V, X5R, 10%, 0603, T=0,8mm; Manufacturer_Part_Number: CC0603KRX5R6BB225; Manufacturer: YAGEO; Alternate_Manufacturer_Part_Number: C0603C225K8PACTU; Alternate_Manufacturer: KEMET; Provided_By: SUBCO; ECCN_US: EAR99; ECCN_EU: NEC
C8-C11 C14-C17 C20-C22 C24 C25 C28-C34 C37 = MCD-00102: Capacitor, MLCC, 100nF, 16V, X7R, 10%, 0402, T=0,5mm; Manufacturer_Part_Number: CC0402KRX7R7BB104; Manufacturer: YAGEO; Alternate_Manufacturer_Part_Number: GCM155R71C104KA55D; Alternate_Manufacturer: MURATA; Provided_By: SUBCO; ECCN_US: EAR99; ECCN_EU: NEC
C19 = MCD-00011: Capacitor, MLCC, 10nF, 16V, X7R, 10%, 0402, T=0.5mm; Manufacturer_Part_Number: CC0402KRX7R7BB103; Manufacturer: YAGEO; Provided_By: SUBCO; ECCN_US: EAR99; ECCN_EU: NEC
C23 C36 = MCD-00010: Capacitor, MLCC, 1uF, 16V, X5R, 10%, 0603, T=0,8mm; Manufacturer_Part_Number: CC0603KRX5R7BB105; Manufacturer: YAGEO; Provided_By: SUBCO; ECCN_US: EAR99; ECCN_EU: NEC
C35 = MCD-00009: as C84 on sheet USB
CN1 = MCD-00028: USB-MICRO-B, 0.65mm, RA, SMT, Bottom Mount,; Manufacturer_Part_Number: 1050170001; Manufacturer: MOLEX; Part_Type: Connector; Provided_By: SUBCO
CN2 = MCD-00029: Header, 4x1, 2,54mm, VR, TH, Height 5.84mm/2.54mm; Manufacturer_Part_Number: TSW-104-07-x-S; Manufacturer: SAMTEC; Part_Type: Connector; Provided_By: SUBCO
CN3 CN4 = MCD-00214: Header, 2x1, 2,54mm, VR, TH, Height 5.84mm/10.16mm; Part_Type: Connector; Manufacturer_Part_Number: TSW-102-09-x-S; Manufacturer: SAMTEC; Provided_By: SUBCO
CN5 = MCD-01226: Header 5x2, 1.27mm, Dual row, Straight, Surface mount, vertical male connector. 3.05mm lead. Mates with FFSD connector. Footprint compatible with FTSH-107-01-L-DV,-K,-A,-P,-ES (STDC14 MEDIUM); Manufacturer_Part_Number: FTSH-105-01-L-DV-K; Manufacturer: SAMTEC; Alternate_Manufacturer_Part_Number: P127B-2x05MGF-079-1A; Alternate_Manufacturer: JIUBABA; Provided_By: SUBCO
D1-D3 = MCD-00034: Manufacturer: STMICROELECTRONICS; Part_Type: Diode; BMS_Part_Number: 9151097; Provided_By: SUBCO with ST control; ECCN_US: EAR99; ECCN_EU: NEC
HW6-HW8 = MCD-00043: SHUNT 2.54mm BLACK; Manufacturer: SAMTEC; Part_Type: Mechanical; Alternate_Manufacturer_Part_Number: 316102S111A; Alternate_Manufacturer: JIUBABA; Provided_By: SUBCO
JP1 = MCD-00045: Header, 2x1, 2,54mm, VR, TH, Height 5.84mm/2.54mm; Part_Type: Connector; Manufacturer_Part_Number: TSW-102-07-x-S; Manufacturer: SAMTEC; Alternate_Manufacturer_Part_Number: 313102S111116;313102S111116; Alternate_Manufacturer: JIUBABA; LIANYI; Provided_By: SUBCO
JP3 = MCD-00683: Header, 2x1, 2,54mm, VR, TH, Height 5.84mm/2.54mm - Shunt Fitted by default; Part_Type: Connector; Manufacturer_Part_Number: TSW-102-07-x-S; Manufacturer: SAMTEC; Alternate_Manufacturer_Part_Number: 313102S111116; Alternate_Manufacturer: LIANYI; Provided_By: SUBCO
LD4 = MCD-00051: LED Bicolor; Part_Type: Display; Manufacturer_Part_Number: HSMF-A201-A00J1; Manufacturer: AVAGO TECHNOLOGIES; Alternate_Manufacturer_Part_Number: LE-RGW35280; Alternate_Manufacturer: EVERLUCK; Provided_By: SUBCO; ECCN_US: EAR99; ECCN_EU: NEC
LD6 = MCD-00049: LED, Red, 0603; Manufacturer_Part_Number: 19-213-R6C-AP1Q2B/3T; Manufacturer: EVERLIGHT; Part_Type: Display; Provided_By: SUBCO; ECCN_US: EAR99; ECCN_EU: NEC
R1 R4 = MCD-00223: Resistor,100K,0603,1%,1/10W; Manufacturer_Part_Number: RC0603FR-07100KL; Manufacturer: YAGEO; Provided_By: SUBCO; ECCN_US: EAR99; ECCN_EU: NEC
R2 = MCD-00070: Resistor,1K,0603,1%,1/10W; Manufacturer_Part_Number: RC0603FR-071KL; Manufacturer: YAGEO; Provided_By: SUBCO; ECCN_US: EAR99; ECCN_EU: NEC
R3 R10 R11 R13 R23 R29 = MCD-00189: Resistor,22R,0402,1%,1/16W; Manufacturer_Part_Number: RC0402FR-0722RL; Manufacturer: YAGEO; Provided_By: SUBCO; ECCN_US: EAR99; ECCN_EU: NEC
R5 R17 R21 R67 = MCD-00119: Resistor,100R,0402,1%,1/16W; Manufacturer_Part_Number: RC0402FR-07100RL; Manufacturer: YAGEO; Provided_By: SUBCO; ECCN_US: EAR99; ECCN_EU: NEC
R6 = MCD-00185: Resistor,3K,0402,1%,1/16W; Manufacturer_Part_Number: RC0402FR-073KL; Manufacturer: YAGEO; Provided_By: SUBCO; ECCN_US: EAR99; ECCN_EU: NEC
R7 = MCD-00220: Resistor,10K,0603,1%,1/10W; Manufacturer_Part_Number: RC0603FR-0710KL; Manufacturer: YAGEO; Provided_By: SUBCO; ECCN_US: EAR99; ECCN_EU: NEC
R8 R9 = MCD-00197: Resistor,330R,0603,1%,1/10W; Manufacturer_Part_Number: RC0603FR-07330RL; Manufacturer: YAGEO; BMS_Part_Number: 9129729; Provided_By: SUBCO; ECCN_US: EAR99; ECCN_EU: NEC
R14 R18 R20 = MCD-00065: Resistor,4K7,0402,1%,1/16W; Manufacturer_Part_Number: RC0402FR-074K7L; Manufacturer: YAGEO; Alternate_Manufacturer_Part_Number: RT0402FRE074K7L; Provided_By: SUBCO; ECCN_US: EAR99; ECCN_EU: NEC
R15 = MCD-00055: Resistor,2K7,0402,1%,1/16W; Manufacturer_Part_Number: RC0402FR-072K7L; Manufacturer: YAGEO; Provided_By: SUBCO; ECCN_US: EAR99; ECCN_EU: NEC
R22 R24 = MCD-00053: as R63 on sheet USB
SB1 SB5 = MCD-00071: as SB74 on sheet Ethernet
U1 U10 = MCD-00264: Dual bit dual supply bus transceiver; Part_Type: IC; Manufacturer: TEXAS INSTRUMENTS; Provided_By: SUBCO; ECCN_US: EAR99; ECCN_EU: NEC
U2 = MCD-00159: 500mA, Enhanced single channel power switches with active high enable pin; Part_Type: IC; Manufacturer: STMICROELECTRONICS; Alternate_Manufacturer_Part_Number: TPS2051C; Alternate_Manufacturer: TEXAS INSTRUMENTS; BMS_Part_Number: 9159009; Provided_By: SUBCO with ST control; ECCN_US: EAR99; ECCN_EU: NEC
U3 U4 = MCD-00170: as U22 on sheet USB
U5 = MCD-00649: Common mode filter with ESD protection for USB 2.0 interface; Part_Type: Diode; Manufacturer: STMICROELECTRONICS; BMS_Part_Number: 9151138; Provided_By: SUBCO with ST control; ECCN_US: EAR99; ECCN_EU: NEC
U6 = MCD-00251: as U21 on sheet USB
U7 = MCD-00596: STM32F723IEK  (STM32F7) BGA176; Part_Type: IC; Manufacturer_Part_Number: STM32F723IEK6; Manufacturer: STMICROELECTRONICS; BMS_Part_Number: 9175300; Provided_By: SUBCO with ST control; ECCN_US: 3A991A2; ECCN_EU: NEC
U8 U24 = MCD-00136: Dual Transil array for ESD protection; Part_Type: Diode; Manufacturer: STMICROELECTRONICS; BMS_Part_Number: 9151112; Provided_By: SUBCO with ST control; ECCN_US: EAR99; ECCN_EU: NEC
U9 = MCD-00086: Ultra low drop-low noise BiCMOS voltage, regulators low ESR capacitors compatible; Manufacturer: STMICROELECTRONICS; Part_Type: IC; BMS_Part_Number: 9176161; Provided_By: SUBCO with ST control; ECCN_US: EAR99; ECCN_EU: NEC
X1 = MCD-00597: Oscillator 25Mhz, +-50ppm, Vcc:3.3V typ, square wave: [0.1Vcc;0.9Vcc], Enable pin, SMD; Manufacturer_Part_Number: NZ2520SH 25MHz END4869C; Manufacturer: NDK; Alternate_Manufacturer_Part_Number: NZ2520SB 25MHz END4869B; Part_Type: Crystal_Osc; BMS_Part_Number: 9157050; Provided_By: SUBCO; ECCN_US: EAR99; ECCN_EU: NEC

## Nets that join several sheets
3V3: Connectors (6 pins), Power_Board (JP5.1 SB2.2 SB6.1 TP1.1), MCU_144_POWER (SB13.1), USB (R56.1 R65.2 R66.2), Ethernet (L1.2)
5V: Connectors (CN8.9 CN11.18), Power_Board (8 pins), USB (U18.5), ST_LINK_V3E (R15.1)
5V_EXT: Connectors (CN11.6), Power_Board (JP2.5), ST_LINK_V3E (D2.1)
5V_USB_CHGR: Power_Board (JP2.7), ST_LINK_V3E (8 pins)
5V_USB_STLK: Connectors (CN12.8), Power_Board (JP2.1), ST_LINK_V3E (C1.2 U2.1)
5V_VIN: Power_Board (C41.2 JP2.3 U12.2 U12.4), ST_LINK_V3E (D1.1)
AGND: Connectors (C65.1 CN10.3 CN12.32), MCU_144_POWER (6 pins)
GND: Connectors (30 pins), Power_Board (15 pins), MCU_144_IOs (15 pins), MCU_144_POWER (26 pins), USB (13 pins), Ethernet (22 pins), ST_LINK_V3E (111 pins)
VBAT: Connectors (CN11.33), MCU_144_POWER (C61.2 SB52.1 U14.6)
VDD: Connectors (CN11.5 SB11.1), Power_Board (JP5.2), MCU_144_IOs (B1.1 B1.2), MCU_144_POWER (JP4.1), USB (R61.1), Ethernet (7 pins), ST_LINK_V3E (7 pins)
VDD_MCU: MCU_144_IOs (R34.2), MCU_144_POWER (26 pins)
VDDA: Connectors (CN10.1), MCU_144_POWER (6 pins)
VIN: Connectors (CN8.15 CN11.24), Power_Board (C42.2 U12.3)
VREFP: Connectors (C65.2 SB42.2), MCU_144_POWER (C58.2 C64.1 R36.2 U14.32)
ARD_D0_RX: Connectors (CN10.16), MCU_144_IOs (SB66.1 SB68.2)
ARD_D1_TX: Connectors (CN10.14), MCU_144_IOs (SB8.1 SB18.2)
BOOT0: Connectors (CN11.7), MCU_144_IOs (R33.1 U14.138)
NRST: Connectors (CN8.5 CN11.14), MCU_144_IOs (5 pins), Ethernet (SB74.1)
PA0: Connectors (CN11.28 SB75.1), MCU_144_IOs (SB58.2 U14.34)
PA1: Connectors (CN11.30), MCU_144_IOs (SB57.1 U14.35)
PA2: Connectors (CN12.35), MCU_144_IOs (SB72.1 U14.36)
PA3: Connectors (CN9.1 CN12.37), MCU_144_IOs (U14.37)
PA4: Connectors (CN7.17 CN11.32), MCU_144_IOs (U14.40)
PA5: Connectors (CN7.10 CN12.11 SB47.1), MCU_144_IOs (U14.41)
PA6: Connectors (CN7.12 CN12.13), MCU_144_IOs (U14.42)
PA7: Connectors (CN12.15 SB33.2), MCU_144_IOs (SB31.1 U14.43)
PA8: Connectors (CN12.23), MCU_144_IOs (TP4.1 U14.100)
PA9: Connectors (CN12.21), MCU_144_IOs (SB23.1 U14.101)
PA10: Connectors (CN12.33), MCU_144_IOs (SB24.1 U14.102)
PA11: Connectors (SB16.2), MCU_144_IOs (SB21.1 U14.103)
PA12: Connectors (SB17.2), MCU_144_IOs (SB22.1 U14.104)
PA13: Connectors (CN11.13), MCU_144_IOs (U14.105)
PA14: Connectors (CN11.15), MCU_144_IOs (U14.109)
PA15: Connectors (CN7.9 CN11.17), MCU_144_IOs (U14.110), ST_LINK_V3E (CN5.10 U8.1)
PB0: Connectors (CN10.31 CN11.34 SB39.1), MCU_144_IOs (U14.46)
PB1: Connectors (CN9.7 CN12.24), MCU_144_IOs (U14.47)
PB2: Connectors (CN12.22 SB63.1 SB69.1), MCU_144_IOs (U14.48)
PB3: Connectors (CN12.31 SB26.1), MCU_144_IOs (SB32.2 U14.133)
PB4: Connectors (CN7.19 CN12.27), MCU_144_IOs (U14.134)
PB5: Connectors (CN7.13 CN12.29 SB35.2), MCU_144_IOs (U14.135)
PB6: Connectors (CN12.17 SB61.1), MCU_144_IOs (SB8.2 SB9.2 U14.136)
PB7: Connectors (CN11.21), MCU_144_IOs (SB34.2 SB68.1 U14.137)
PB8: Connectors (CN7.2 CN12.3 SB62.1), MCU_144_IOs (U14.139)
PB9: Connectors (CN7.4 CN12.5 SB55.1), MCU_144_IOs (U14.140)
PB10: Connectors (CN10.32 CN12.25), MCU_144_IOs (U14.69)
PB11: Connectors (CN10.34 CN12.18), MCU_144_IOs (U14.70)
PB12: Connectors (CN7.7 CN12.16), MCU_144_IOs (U14.73)
PB13: Connectors (CN12.30 SB7.1), MCU_144_IOs (JP6.1 U14.74)
PB14: Connectors (CN12.28 R72.1), MCU_144_IOs (U14.75)
PB15: Connectors (CN7.3 CN12.26), MCU_144_IOs (U14.76)
PC0: Connectors (CN9.3 CN11.38), MCU_144_IOs (U14.26)
PC1: Connectors (CN11.36), MCU_144_IOs (SB64.2 U14.27)
PC2: Connectors (CN11.35 SB53.1), MCU_144_IOs (U14.28)
PC3: Connectors (CN9.5 CN11.37), MCU_144_IOs (U14.29)
PC4: Connectors (CN12.34), MCU_144_IOs (SB36.2 U14.44)
PC5: Connectors (CN12.6), MCU_144_IOs (SB29.2 U14.45)
PC6: Connectors (CN7.1 CN12.4), MCU_144_IOs (U14.96)
PC7: Connectors (CN7.11 CN12.19), MCU_144_IOs (U14.97)
PC8: Connectors (CN8.2 SB14.2), MCU_144_IOs (U14.98)
PC9: Connectors (CN8.4 SB15.1), MCU_144_IOs (U14.99)
PC10: Connectors (CN8.6 CN11.1), MCU_144_IOs (U14.111)
PC11: Connectors (CN8.8 CN11.2), MCU_144_IOs (U14.112)
PC12: Connectors (CN8.10 CN11.3), MCU_144_IOs (U14.113)
PC13: Connectors (CN11.23), MCU_144_IOs (SB51.2 U14.7)
PC14: Connectors (CN11.25), MCU_144_IOs (SB41.1)
PC15: Connectors (CN11.27), MCU_144_IOs (SB40.1)
PD0: Connectors (CN9.25 CN11.57), MCU_144_IOs (U14.114)
PD1: Connectors (CN9.27 CN11.55), MCU_144_IOs (U14.115)
PD2: Connectors (CN8.12 CN11.4), MCU_144_IOs (U14.116)
PD3: Connectors (CN9.10 CN11.40), MCU_144_IOs (U14.117)
PD4: Connectors (CN9.8 CN11.39), MCU_144_IOs (U14.118)
PD5: Connectors (CN9.6 CN11.41), MCU_144_IOs (U14.119)
PD6: Connectors (CN9.4 CN11.43), MCU_144_IOs (U14.122)
PD7: Connectors (CN9.2 CN11.45), MCU_144_IOs (U14.123)
PD8: Connectors (SB82.2), MCU_144_IOs (SB18.1 SB19.1 U14.77)
PD9: Connectors (SB81.1), MCU_144_IOs (SB12.1 SB66.2 U14.78)
PD10: Connectors (CN12.65), MCU_144_IOs (SB77.1 U14.79)
PD11: Connectors (CN10.23 CN12.45), MCU_144_IOs (U14.80)
PD12: Connectors (CN10.21 CN12.43), MCU_144_IOs (U14.81)
PD13: Connectors (CN10.19 CN12.41), MCU_144_IOs (U14.82)
PD14: Connectors (CN7.16 CN12.46), MCU_144_IOs (U14.85)
PD15: Connectors (CN7.18 CN12.48), MCU_144_IOs (U14.86)
PE0: Connectors (CN10.33 CN12.64), MCU_144_IOs (U14.141)
PE1: Connectors (CN11.61 R71.1), MCU_144_IOs (U14.142)
PE2: Connectors (CN10.25 CN11.46 SB67.2), MCU_144_IOs (U14.1)
PE3: Connectors (CN9.22 CN11.47), MCU_144_IOs (U14.2)
PE4: Connectors (CN9.16 CN11.48), MCU_144_IOs (U14.3)
PE5: Connectors (CN9.18 CN11.50), MCU_144_IOs (U14.4)
PE6: Connectors (CN11.62 SB71.2 SB73.2), MCU_144_IOs (U14.5)
PE7: Connectors (CN10.20 CN12.44), MCU_144_IOs (U14.58)
PE8: Connectors (CN10.18 CN12.40), MCU_144_IOs (U14.59)
PE9: Connectors (CN12.52 SB28.2 SB70.1), MCU_144_IOs (U14.60)
PE10: Connectors (CN10.24 CN12.47), MCU_144_IOs (U14.63)
PE11: Connectors (CN10.6 CN12.56), MCU_144_IOs (U14.64)
PE12: Connectors (CN10.26 CN12.49), MCU_144_IOs (U14.65)
PE13: Connectors (CN10.10 CN12.55), MCU_144_IOs (U14.66)
PE14: Connectors (CN10.8 CN12.51), MCU_144_IOs (U14.67)
PE15: Connectors (CN10.30 CN12.53), MCU_144_IOs (U14.68)
PF0: Connectors (CN9.21 CN11.53), MCU_144_IOs (U14.10)
PF1: Connectors (CN9.19 CN11.51), MCU_144_IOs (U14.11)
PF2: Connectors (CN9.17 CN11.52), MCU_144_IOs (U14.12)
PF3: Connectors (CN7.20 CN12.58), MCU_144_IOs (U14.13)
PF4: Connectors (CN12.38 SB38.1), MCU_144_IOs (U14.14)
PF5: Connectors (CN12.36 SB48.1), MCU_144_IOs (U14.15)
PF6: Connectors (CN11.9 SB54.1), MCU_144_IOs (U14.18)
PF7: Connectors (CN9.26 CN11.11), MCU_144_IOs (U14.19)
PF8: Connectors (CN9.24 CN11.54), MCU_144_IOs (U14.20)
PF9: Connectors (CN9.28 CN11.56), MCU_144_IOs (U14.21)
PF10: Connectors (CN12.42 SB60.1), MCU_144_IOs (U14.22)
PF11: Connectors (CN12.62 SB65.1), MCU_144_IOs (U14.49)
PF12: Connectors (CN12.59 SB37.1), MCU_144_IOs (U14.50)
PF13: Connectors (CN12.57 SB49.1), MCU_144_IOs (U14.53)
PF14: Connectors (CN12.50 SB50.1), MCU_144_IOs (U14.54)
PF15: Connectors (CN12.60), MCU_144_IOs (U14.55)
PG0: Connectors (CN9.29 CN11.59), MCU_144_IOs (U14.56)
PG1: Connectors (CN9.30 CN11.58), MCU_144_IOs (U14.57)
PG2: Connectors (CN8.14 CN11.42), MCU_144_IOs (U14.87)
PG3: Connectors (CN8.16 CN11.44), MCU_144_IOs (U14.88)
PG4: Connectors (CN12.69), MCU_144_IOs (U14.89)
PG5: Connectors (CN12.68), MCU_144_IOs (U14.90)
PG6: Connectors (CN12.70 SB59.1), MCU_144_IOs (U14.91)
PG7: Connectors (CN12.67), MCU_144_IOs (SB76.2 U14.92)
PG8: Connectors (CN12.66), MCU_144_IOs (U14.93)
PG9: Connectors (CN11.63), MCU_144_IOs (U14.124)
PG10: Connectors (CN11.66), MCU_144_IOs (U14.125)
PG11: Connectors (CN11.70), MCU_144_IOs (SB27.2 U14.126)
PG12: Connectors (CN10.2 CN11.65), MCU_144_IOs (U14.127)
PG13: Connectors (CN11.68), MCU_144_IOs (SB30.2 U14.128)
PG14: Connectors (CN10.12 CN12.61), MCU_144_IOs (U14.129)
PG15: Connectors (CN11.64), MCU_144_IOs (U14.132)
PH0: Connectors (CN11.29), MCU_144_IOs (SB46.2)
PH1: Connectors (CN11.31), MCU_144_IOs (SB44.2)
RMII_CRS_DV: MCU_144_IOs (SB31.2), Ethernet (R41.1)
RMII_MDC: MCU_144_IOs (SB64.1), Ethernet (U15.13)
RMII_MDIO: MCU_144_IOs (SB72.2), Ethernet (R47.1 U15.12)
RMII_REF_CLK: MCU_144_IOs (SB57.2), Ethernet (R49.1)
RMII_RXD0: MCU_144_IOs (SB36.1), Ethernet (R44.1)
RMII_RXD1: MCU_144_IOs (SB29.1), Ethernet (R45.1)
RMII_TX_EN: MCU_144_IOs (SB27.1), Ethernet (U15.16)
RMII_TXD0: MCU_144_IOs (SB30.1), Ethernet (U15.17)
RMII_TXD1: MCU_144_IOs (JP6.2), Ethernet (U15.18)
STLK_MCO: MCU_144_IOs (SB45.2), ST_LINK_V3E (C5.2 R5.2)
T_VCP_RX: MCU_144_IOs (SB12.2 SB34.1), ST_LINK_V3E (CN5.13 R23.2 U24.1)
T_VCP_TX: MCU_144_IOs (SB9.1 SB19.2), ST_LINK_V3E (CN5.14 R3.1 U24.3)
USB_FS_ID: MCU_144_IOs (SB24.2), USB (CN13.4 U22.1)
USB_FS_N: MCU_144_IOs (SB21.2), USB (U19.1)
USB_FS_OVCR: MCU_144_IOs (SB76.1), USB (LD7.2 R61.2 U18.3)
USB_FS_P: MCU_144_IOs (SB22.2), USB (U19.3)
USB_FS_PWR_EN: MCU_144_IOs (SB77.2), USB (R56.2 U18.4)
USB_FS_VBUS: MCU_144_IOs (R60.1), USB (5 pins)

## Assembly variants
H743ZI: not fitted C62 C63 C69 C70 C71 C72 CN2 CN11 CN12 R35 R54 R55 R67 SB1 SB3 SB4 SB5 SB7 SB9 SB14 SB15 SB16 SB17 SB18 SB20 SB33 SB34 SB37 SB40 SB41 SB44 SB46 SB47 SB49 SB50 SB55 SB58 SB61 SB62 SB65 SB66 SB69 SB70 SB78 SB79 X3
H7A3ZI: not fitted C62 C63 C69 C70 C71 C72 C73 C74 C75 C76 C77 C78 C79 C80 C81 C82 C83 C85 CN2 CN11 CN12 CN14 HW3 JP6 L1 R35 R40 R41 R42 R43 R44 R45 R46 R47 R48 R49 R50 R51 R52 R53 R54 R55 R57 R58 R59 R67 R75 R76 R77 R78 SB1 SB3 SB4 SB5 SB7 SB9 SB14 SB15 SB16 SB17 SB18 SB20 SB27 SB29 SB30 SB31 SB34 SB35 SB36 SB38 SB40 SB41 SB44 SB46 SB47 SB48 SB54 SB55 SB57 SB58 SB60 SB61 SB62 SB64 SB66 SB69 SB70 SB72 SB74 SB78 SB79 U15 U16 U17 X3 X4
H7B3ZI: not fitted C62 C63 C69 C70 C71 C72 C73 C74 C75 C76 C77 C78 C79 C80 C81 C82 C83 C85 CN2 CN11 CN12 CN14 HW3 JP6 L1 R35 R40 R41 R42 R43 R44 R45 R46 R47 R48 R49 R50 R51 R52 R53 R54 R55 R57 R58 R59 R67 R75 R76 R77 R78 SB1 SB3 SB4 SB5 SB7 SB9 SB14 SB15 SB16 SB17 SB18 SB20 SB27 SB29 SB30 SB31 SB34 SB35 SB36 SB38 SB40 SB41 SB44 SB46 SB47 SB48 SB54 SB55 SB57 SB58 SB60 SB61 SB62 SB64 SB66 SB69 SB70 SB72 SB74 SB78 SB79 U15 U16 U17 X3 X4
H753ZI: not fitted C62 C63 C69 C70 C71 C72 CN2 CN11 CN12 R35 R54 R55 R67 SB1 SB3 SB4 SB5 SB7 SB9 SB14 SB15 SB16 SB17 SB18 SB20 SB33 SB34 SB37 SB40 SB41 SB44 SB46 SB47 SB49 SB50 SB55 SB58 SB61 SB62 SB65 SB66 SB69 SB70 SB78 SB79 X3
H723ZG: not fitted C62 C63 C69 C70 C71 C72 CN2 CN11 CN12 R35 R54 R55 R67 SB1 SB3 SB4 SB5 SB7 SB9 SB14 SB15 SB16 SB17 SB18 SB20 SB33 SB34 SB37 SB40 SB41 SB44 SB46 SB47 SB49 SB50 SB55 SB58 SB61 SB62 SB65 SB66 SB69 SB70 SB78 SB79 X3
